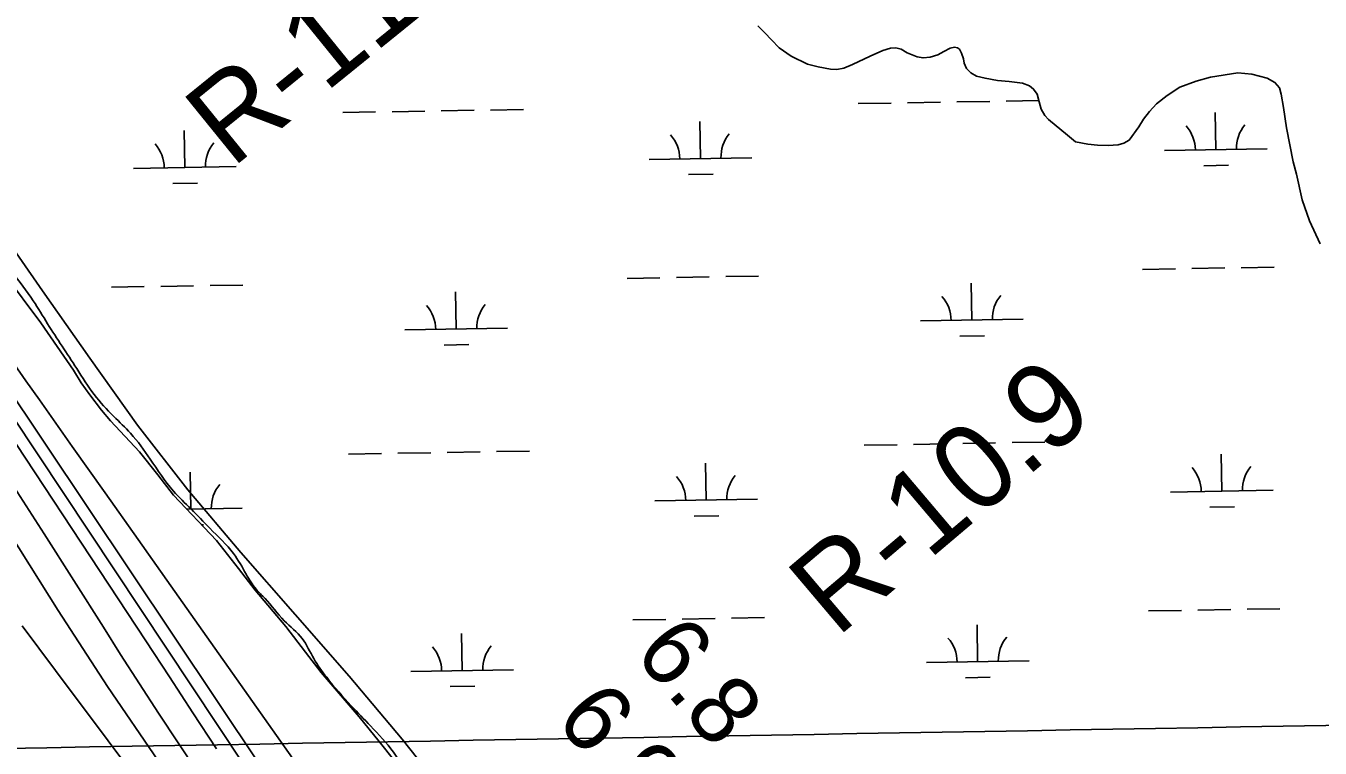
# Model space of a CAD drawing. Extents: x 3892998 to 3931244, y 278583 to 304547.
# Drawn here: x 3913620 to 3914880, y 290357 to 291060 of the extents above; entities that cross this region are included whole.
import ezdxf

# ---------------------------------------------------------------- set-up
doc = ezdxf.new("R2010")
doc.units = 0
for name, color, linetype in [('V-GRID-MAJR', 7, 'Continuous'), ('V-RIVR-EDGE', 7, 'Continuous'), ('V-RIVR-RANG', 7, 'Continuous'), ('V-RIVR-RANG-IDEN', 7, 'Continuous'), ('V-RRAP-FSHR', 7, 'Continuous'), ('V-TOPO-DPTH', 7, 'Continuous'), ('V-TOPO-MAJR', 7, 'Continuous'), ('V-TOPO-MINR', 7, 'Continuous'), ('V-TOPO-SHOR', 7, 'Continuous'), ('V-WETL-SWMP', 7, 'Continuous')]:
    doc.layers.add(name, color=color, linetype=linetype)

msp = doc.modelspace()

# ---------------------------------------------------------------- linework, layer by layer
at = {"layer": 'V-GRID-MAJR'}
msp.add_spline([(3897162.9, 290075.2), (3902475.5, 290165.2), (3907788.2, 290256), (3913100.9, 290347.6), (3918413.5, 290440), (3923726.1, 290533.1), (3929038.7, 290627)], degree=3, dxfattribs=at)
at = {"layer": 'V-RIVR-EDGE'}
for points in [[(3912905.5, 291820.1), (3912916.2, 291798.1), (3912921.4, 291787), (3912931.4, 291765), (3912935.9, 291747.6), (3912940.4, 291735.8), (3912955, 291711.4), (3912961.5, 291684.5), (3912964.3, 291665.7), (3912967, 291653.5), (3912976, 291634.4), (3912985.7, 291613.1), (3912986.4, 291604.4), (3912990.5, 291597.4), (3912997.1, 291593.3), (3913007.6, 291587), (3913014.2, 291580.7), (3913019.4, 291567.4), (3913027, 291556.3), (3913048.2, 291537.1), (3913061.4, 291520.7), (3913079.1, 291496.6), (3913103, 291468.4), (3913127.3, 291438.4), (3913184.9, 291379.7), (3913206.1, 291354.6), (3913225.2, 291327.8), (3913253.3, 291286.6), (3913265.1, 291274.8), (3913279.3, 291262.2), (3913304.7, 291231.5), (3913329.3, 291201.2), (3913355.7, 291168.4), (3913376.5, 291143.3), (3913400.8, 291111.5), (3913434.5, 291068.6), (3913468.5, 291022.2), (3913495.2, 290985.6), (3913514.6, 290959.1), (3913570.4, 290873.7), (3913590.9, 290842), (3913606.5, 290820.3), (3913627.3, 290792.1), (3913641.2, 290769.8), (3913669.6, 290726.2), (3913686.6, 290700.8), (3913705.7, 290679.5), (3913722, 290663.1), (3913741.1, 290638), (3913763.7, 290606.9), (3913781, 290589.5)], [(3913781, 290589.5), (3913799.1, 290570.6), (3913822.3, 290545.9), (3913834.5, 290526), (3913844.2, 290511.3), (3913852.9, 290502.3), (3913871.6, 290480.6), (3913889, 290463.2), (3913900.4, 290443.7), (3913912.9, 290425.5), (3913936.9, 290397.6), (3913955.6, 290378.1), (3913977.8, 290352.6), (3913994.1, 290327.5), (3914016.3, 290296.8), (3914036.1, 290274.5), (3914055.2, 290244.5), (3914064.9, 290220.5), (3914103.3, 290142.1), (3914120.3, 290106.5), (3914139, 290073.4), (3914155.3, 290049.3), (3914170.6, 290031.5), (3914200.4, 289990.7), (3914235.5, 289947.1), (3914261.5, 289911.2), (3914286.5, 289877.4), (3914313.2, 289840.1), (3914336.4, 289806.3), (3914349.6, 289786), (3914375.3, 289751.2), (3914395.7, 289725.4), (3914439.8, 289677.9), (3914471.4, 289643.4), (3914507.5, 289604.3), (3914554.7, 289546.7), (3914583.5, 289515), (3914618.9, 289470.3), (3914642.5, 289441.7), (3914696, 289378.6), (3914731.4, 289337.8), (3914757.4, 289307.8), (3914791.8, 289266.3), (3914814, 289240.1), (3914843.8, 289203.8), (3914862.6, 289182.9), (3914891.7, 289150.8), (3914929.6, 289103.4), (3914947.6, 289081), (3914975.4, 289049.6), (3915002.1, 289021.4)]]:
    msp.add_spline(points, degree=3, dxfattribs=at)
at = {"layer": 'V-RRAP-FSHR'}
msp.add_lwpolyline([(3913590.5, 290867.4), (3913636.3, 290801.8), (3913682.3, 290736.4), (3913728.6, 290671.1), (3913777.6, 290607.9), (3913829.5, 290547.1), (3913882.1, 290486.8), (3913934.8, 290426.6), (3913986.3, 290365.4), (3914036.1, 290302.7), (3914079.6, 290235.7), (3914110.4, 290162), (3914147.3, 290091.2), (3914193.5, 290025.6), (3914241.1, 289961.7), (3914289.2, 289897.7), (3914337.2, 289833.7), (3914385.6, 289770.2), (3914434.6, 289706.8), (3914485.6, 289645.2), (3914540.7, 289587.2), (3914594.8, 289528.3), (3914646.2, 289467.1)], dxfattribs=at)
at = {"layer": 'V-TOPO-DPTH'}
for points in [[(3913805.5, 290355.8), (3913782.7, 290390.9), (3913759.8, 290426), (3913736.8, 290461), (3913565.6, 290720.7)], [(3913565.6, 290720.7), (3913736.8, 290461), (3913759.8, 290426), (3913782.7, 290390.9), (3913805.5, 290355.8)], [(3913596.7, 290716.2), (3913931.4, 290215.1)], [(3913786.9, 290333.8), (3913749.2, 290390.5), (3913712.3, 290447.8), (3913695.7, 290474.2), (3913666.8, 290519.8), (3913637.8, 290565.3), (3913608.7, 290610.8)], [(3913786.9, 290333.8), (3913749.2, 290390.5), (3913712.3, 290447.8), (3913695.7, 290474.2), (3913666.8, 290519.8), (3913637.8, 290565.3), (3913608.7, 290610.8)], [(3913604.6, 290565.6), (3913651.4, 290490.7), (3913699.5, 290416.7), (3913749.3, 290343.9)], [(3913604.6, 290565.6), (3913651.4, 290490.7), (3913699.5, 290416.7), (3913749.3, 290343.9)]]:
    msp.add_lwpolyline(points, dxfattribs=at)
at = {"layer": 'V-TOPO-MAJR'}
msp.add_lwpolyline([(3913907.2, 290087.2), (3913648.9, 290432), (3913616.6, 290475.6)], dxfattribs=at)
at = {"layer": 'V-TOPO-MINR'}
for points in [[(3914908.6, 288972.1), (3914492.4, 289530.5), (3914479.7, 289547.5), (3914466.9, 289564.5), (3914454, 289581.4), (3914441.1, 289598.3), (3914225.4, 289878.6), (3914189, 289926.2), (3914152.6, 289973.8), (3914116.3, 290021.6), (3914080.1, 290069.4), (3914050.7, 290108.3), (3914029.4, 290136.8), (3914008.3, 290165.4), (3913987.5, 290194.2), (3913966.9, 290223.1), (3913761.2, 290514.6), (3913729.3, 290559.8), (3913697.3, 290605.1), (3913665.3, 290650.3), (3913633.4, 290695.6), (3913620.2, 290714.2), (3913594.7, 290750.1)], [(3913805.5, 290355.8), (3913782.7, 290390.9), (3913759.8, 290426), (3913736.8, 290461), (3913565.6, 290720.7)], [(3913831.8, 290340.8), (3913581.1, 290718.4)], [(3913931.4, 290215.1), (3913596.7, 290716.2)], [(3913786.9, 290333.8), (3913749.2, 290390.5), (3913712.3, 290447.8), (3913695.7, 290474.2), (3913666.8, 290519.8), (3913637.8, 290565.3), (3913608.7, 290610.8)], [(3913749.3, 290343.9), (3913699.5, 290416.7), (3913651.4, 290490.7), (3913604.6, 290565.6)]]:
    msp.add_lwpolyline(points, dxfattribs=at)
at = {"layer": 'V-TOPO-SHOR'}
for points in [[(3914634.2, 290953.3), (3914615.6, 290968.6), (3914612, 290972.7), (3914608.4, 290978.8), (3914606.5, 290985.8), (3914604.4, 290993.4), (3914601, 290998.3), (3914597.2, 291001.6), (3914590.2, 291004), (3914577.4, 291005.6), (3914565.8, 291006.7), (3914553.9, 291008.8), (3914545.5, 291011), (3914539.9, 291014), (3914535.8, 291018.2), (3914533.4, 291023.5), (3914532.7, 291027.7), (3914531, 291033.2), (3914529, 291037.1), (3914526.9, 291038.6), (3914524, 291039), (3914519.7, 291038.2), (3914513.6, 291035), (3914507.7, 291031.7), (3914500.5, 291029.5), (3914493.5, 291028.6), (3914487.7, 291029.6), (3914478, 291033.7), (3914472.1, 291037.2), (3914466.9, 291038.4), (3914461.9, 291038), (3914454.2, 291036), (3914442, 291030.4), (3914424.9, 291022.1), (3914416.2, 291018.8), (3914409.6, 291017.4), (3914403.3, 291017.7), (3914391.4, 291019.8), (3914381.1, 291022.5), (3914365, 291030.2), (3914353.4, 291038.6), (3914345.8, 291046.2), (3914339.5, 291053.2), (3914332.5, 291059.8)], [(3914880, 290847.7), (3914869.7, 290870.1), (3914862.5, 290890.5), (3914856.9, 290915.3), (3914853.7, 290927.3), (3914847.4, 290960.6), (3914844.3, 290980.3), (3914842, 290993.3), (3914840.4, 290999.4), (3914836, 291004.7), (3914828.4, 291008.9), (3914813.4, 291012.7), (3914800, 291014.1), (3914773.2, 291010), (3914759.3, 291006), (3914743.5, 291000), (3914731.1, 290991.9), (3914720.8, 290983.9), (3914714, 290976.6), (3914707.9, 290969.1), (3914703.6, 290961.6), (3914694, 290948.7), (3914688.8, 290945.5), (3914683.3, 290944), (3914673.8, 290943.3), (3914663.2, 290943.7), (3914653.8, 290944.7), (3914641.7, 290946.8), (3914634.2, 290953.3)]]:
    msp.add_lwpolyline(points, dxfattribs=at)
at = {"layer": 'V-WETL-SWMP'}
for p, q in [((3914332.5, 291059.8), (3914339.5, 291053.2)), ((3914339.5, 291053.2), (3914345.8, 291046.2)), ((3914345.8, 291046.2), (3914353.4, 291038.6)), ((3914353.4, 291038.6), (3914365, 291030.2)), ((3914365, 291030.2), (3914381.1, 291022.5)), ((3914424.9, 291022.1), (3914442, 291030.4)), ((3914442, 291030.4), (3914454.3, 291036)), ((3914454.3, 291036), (3914461.9, 291038)), ((3914461.9, 291038), (3914466.9, 291038.4)), ((3914466.9, 291038.4), (3914472.1, 291037.2)), ((3914472.1, 291037.2), (3914478, 291033.7)), ((3914478, 291033.7), (3914487.7, 291029.6)), ((3914487.7, 291029.6), (3914493.5, 291028.6)), ((3914493.5, 291028.6), (3914500.5, 291029.5)), ((3914500.5, 291029.5), (3914507.7, 291031.7)), ((3914507.7, 291031.7), (3914513.6, 291035)), ((3914513.6, 291035), (3914519.7, 291038.2)), ((3914519.7, 291038.2), (3914524, 291039)), ((3914524, 291039), (3914526.9, 291038.6)), ((3914526.9, 291038.6), (3914529, 291037.1)), ((3914529, 291037.1), (3914531, 291033.2)), ((3914531, 291033.2), (3914532.7, 291027.7)), ((3914381.1, 291022.5), (3914391.4, 291019.8)), ((3914391.4, 291019.8), (3914403.3, 291017.7)), ((3914403.3, 291017.7), (3914409.6, 291017.4)), ((3914409.6, 291017.4), (3914416.2, 291018.8)), ((3914416.2, 291018.8), (3914424.9, 291022.1)), ((3914532.7, 291027.7), (3914533.4, 291023.5)), ((3914533.4, 291023.5), (3914535.8, 291018.2)), ((3914535.8, 291018.2), (3914539.9, 291014)), ((3914539.9, 291014), (3914545.5, 291011)), ((3914545.5, 291011), (3914553.9, 291008.8)), ((3914553.9, 291008.8), (3914565.8, 291006.7)), ((3914565.8, 291006.7), (3914577.4, 291005.6)), ((3914577.4, 291005.6), (3914590.2, 291004)), ((3914590.2, 291004), (3914597.2, 291001.6)), ((3914743.5, 291000), (3914759.3, 291006)), ((3914759.3, 291006), (3914773.2, 291010)), ((3914773.2, 291010), (3914800, 291014.1)), ((3914800, 291014.1), (3914813.4, 291012.7)), ((3914813.4, 291012.7), (3914828.4, 291008.9)), ((3914828.4, 291008.9), (3914836, 291004.7)), ((3914836, 291004.7), (3914840.4, 290999.4)), ((3914597.2, 291001.6), (3914601, 290998.3)), ((3914601, 290998.3), (3914604.4, 290993.4)), ((3914604.4, 290993.4), (3914606.5, 290985.8)), ((3914720.8, 290983.9), (3914731.1, 290991.9)), ((3914731.1, 290991.9), (3914743.5, 291000)), ((3914840.4, 290999.4), (3914842, 290993.3)), ((3914842, 290993.3), (3914844.3, 290980.3)), ((3914072.5, 290977.9), (3914104.5, 290978.4)), ((3914430.4, 290984.1), (3914462.4, 290984.6)), ((3914478.4, 290984.9), (3914510.4, 290985.5)), ((3914526.4, 290985.8), (3914558.4, 290986.3)), ((3914574.4, 290986.6), (3914606.1, 290987.1)), ((3914606.5, 290985.8), (3914608.4, 290978.8)), ((3914608.4, 290978.8), (3914612, 290972.7)), ((3914714, 290976.6), (3914720.8, 290983.9)), ((3914844.3, 290980.3), (3914847.4, 290960.6)), ((3913928.5, 290975.4), (3913960.5, 290976)), ((3913976.5, 290976.2), (3914008.5, 290976.8)), ((3914024.5, 290977.1), (3914056.5, 290977.6)), ((3914276.7, 290930.7), (3914276.1, 290966.7)), ((3914612, 290972.7), (3914615.6, 290968.6)), ((3914615.6, 290968.6), (3914634.2, 290953.3)), ((3914703.6, 290961.6), (3914707.9, 290969.1)), ((3914707.9, 290969.1), (3914714, 290976.6)), ((3914778.5, 290939.4), (3914777.9, 290975.4)), ((3913774.9, 290922), (3913774.2, 290958)), ((3914634.2, 290953.3), (3914641.7, 290946.8)), ((3914694, 290948.7), (3914703.6, 290961.6)), ((3914847.4, 290960.6), (3914853.7, 290927.3)), ((3914641.7, 290946.8), (3914653.8, 290944.7)), ((3914653.8, 290944.7), (3914663.2, 290943.7)), ((3914663.2, 290943.7), (3914673.8, 290943.3)), ((3914673.8, 290943.3), (3914683.3, 290944)), ((3914683.3, 290944), (3914688.8, 290945.5)), ((3914688.8, 290945.5), (3914694, 290948.7)), ((3914226.7, 290929.8), (3914326.7, 290931.5)), ((3914728.5, 290938.5), (3914828.5, 290940.2)), ((3913724.9, 290921.1), (3913824.8, 290922.9)), ((3914265, 290915), (3914289, 290915.5)), ((3914766.8, 290923.7), (3914790.8, 290924.1)), ((3914853.7, 290927.3), (3914856.9, 290915.3)), ((3914856.9, 290915.3), (3914862.5, 290890.5)), ((3913763.1, 290906.4), (3913787.1, 290906.8)), ((3914862.5, 290890.5), (3914869.7, 290870.1)), ((3914869.7, 290870.1), (3914880, 290847.7)), ((3913634.7, 290770.8), (3913599.3, 290818.1)), ((3914205.3, 290814), (3914237.3, 290814.5)), ((3914253.3, 290814.8), (3914285.3, 290815.4)), ((3914301.3, 290815.7), (3914333.3, 290816.2)), ((3914707.1, 290822.7), (3914739.1, 290823.2)), ((3914755.1, 290823.5), (3914787.1, 290824.1)), ((3914803.1, 290824.3), (3914835.1, 290824.9)), ((3913703.5, 290805.3), (3913735.4, 290805.9)), ((3913751.4, 290806.1), (3913783.4, 290806.7)), ((3913799.4, 290807), (3913831.4, 290807.5)), ((3914540.9, 290773.4), (3914540.3, 290809.4)), ((3914039.1, 290764.7), (3914038.4, 290800.7)), ((3913666.3, 290724.5), (3913634.7, 290770.8)), ((3913989.1, 290763.8), (3914089, 290765.5)), ((3914490.9, 290772.5), (3914590.9, 290774.2)), ((3914529.2, 290757.7), (3914553.2, 290758.1)), ((3914027.3, 290749), (3914051.3, 290749.5)), ((3913673.8, 290712.1), (3913666.3, 290724.5)), ((3913682.2, 290700.4), (3913673.8, 290712.1)), ((3913693.6, 290685.7), (3913682.2, 290700.4)), ((3913702.5, 290675.2), (3913693.6, 290685.7)), ((3913730.7, 290645.1), (3913702.5, 290675.2)), ((3914436.1, 290651.5), (3914468.1, 290652)), ((3914484.1, 290652.3), (3914516.1, 290652.8)), ((3914532.1, 290653.1), (3914564.1, 290653.7)), ((3914580.1, 290654), (3914612.1, 290654.5)), ((3913748.5, 290622.6), (3913730.7, 290645.1)), ((3913934.3, 290642.8), (3913966.3, 290643.3)), ((3913982.3, 290643.6), (3914014.3, 290644.2)), ((3914030.3, 290644.4), (3914062.3, 290645)), ((3914078.3, 290645.3), (3914110.3, 290645.8)), ((3914784.3, 290606.7), (3914783.7, 290642.7)), ((3913780.6, 290589.4), (3913780, 290625.4)), ((3914282.4, 290598.1), (3914281.8, 290634)), ((3913763.8, 290602.7), (3913748.5, 290622.6)), ((3913805.7, 290558.7), (3913763.8, 290602.7)), ((3914734.3, 290605.9), (3914834.3, 290607.6)), ((3913776.6, 290589.3), (3913830.6, 290590.2)), ((3914232.5, 290597.2), (3914332.4, 290598.9)), ((3914772.5, 290591.1), (3914796.5, 290591.5)), ((3914270.7, 290582.4), (3914294.7, 290582.8)), ((3913791.1, 290574.1), (3913792.9, 290574.1)), ((3913827.1, 290531.4), (3913805.7, 290558.7)), ((3913843.2, 290510.2), (3913827.1, 290531.4)), ((3913873, 290474.9), (3913843.2, 290510.2)), ((3914712.9, 290490.1), (3914744.9, 290490.6)), ((3914760.9, 290490.9), (3914792.9, 290491.4)), ((3914808.9, 290491.7), (3914840.9, 290492.3)), ((3913892.3, 290450.1), (3913873, 290474.9)), ((3914211, 290481.4), (3914243, 290481.9)), ((3914259, 290482.2), (3914291, 290482.8)), ((3914307, 290483), (3914339, 290483.6)), ((3914546.6, 290440.7), (3914546, 290476.7)), ((3914044.8, 290432.1), (3914044.2, 290468.1)), ((3913907.7, 290430.2), (3913892.3, 290450.1)), ((3914496.7, 290439.9), (3914596.6, 290441.6)), ((3913944.6, 290387), (3913907.7, 290430.2)), ((3913994.8, 290431.2), (3914094.8, 290432.9)), ((3914534.9, 290425.1), (3914558.9, 290425.5)), ((3914033.1, 290416.4), (3914057.1, 290416.8)), ((3913964, 290363.1), (3913944.6, 290387)), ((3913979.4, 290344), (3913964, 290363.1))]:
    msp.add_line(p, q, dxfattribs=at)
for centre, start, end in [((3914221.4, 290930.2), 0.2199, 41.7635), ((3914331.9, 290932.1), 140.2199, 181.7635), ((3914723.3, 290938.9), 0.2199, 41.7635), ((3914833.7, 290940.8), 140.2199, 181.7635), ((3913719.6, 290921.5), 0.2199, 41.7635), ((3913830.1, 290923.4), 140.2199, 181.7635), ((3914485.6, 290772.9), 0.2199, 41.7635), ((3914596.1, 290774.8), 140.2199, 181.7635), ((3913983.8, 290764.2), 0.2199, 41.7635), ((3914094.3, 290766.1), 140.2199, 181.7635), ((3914729, 290606.3), 0.2199, 41.7635), ((3914839.5, 290608.2), 140.2199, 181.7635), ((3913835.8, 290590.8), 140.2199, 181.7635), ((3914227.2, 290597.6), 0.2199, 41.7635), ((3914337.7, 290599.5), 140.2199, 181.7635), ((3914491.4, 290440.3), 0.2199, 41.7635), ((3914601.9, 290442.2), 140.2199, 181.7635), ((3913989.6, 290431.6), 0.2199, 41.7635), ((3914100, 290433.5), 140.2199, 181.7635)]:
    msp.add_arc(centre, 35.2, start, end, dxfattribs=at)

# ---------------------------------------------------------------- texts
at = {"layer": 'V-RIVR-RANG'}
for s, p in [('6.8', (3914210.6, 290448.5)), ('6.9', (3914134.1, 290384.1))]:
    msp.add_text(s, height=67, rotation=310.1083, dxfattribs=at).set_placement(p)
at = {"layer": 'V-RIVR-RANG-IDEN'}
for s, rotation, p in [('R-11.05', 39.0186, (3913820.5, 290920.5)), ('R-10.9', 40.2538, (3914409.5, 290463.5))]:
    msp.add_text(s, height=83, rotation=rotation, dxfattribs=at).set_placement(p)

doc.saveas('drawing.dxf')
